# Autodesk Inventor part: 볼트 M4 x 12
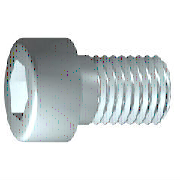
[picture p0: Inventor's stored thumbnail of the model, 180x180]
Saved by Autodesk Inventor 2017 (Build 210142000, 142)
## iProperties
IsCustomPart: 0
Created: 2012-02
Part Number: 볼트 M4 x 12
Material: 강철, 연강
Description: 6각 소켓 머리 캡 나사
Document SubType Name: Modeling
Standard: ISO 4762
Designer: mduedu
Standard Revision: Fourth edition 2004-03-01
Standards Organization: ISO
Language: ko-KR
Size Designation: M4 x 12
Categories: <MemberInstance><Categories><Category DisplayName="조임쇠" InternalName="e4da775c-781d-43d5-af7c-5136215cf5a6" Mnemonic="FSTN"><Category DisplayName="볼트" InternalN
Density: 7.75 g/cm^3
Appearance: 강철
Author: mduedu
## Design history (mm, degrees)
sketch "스케치1"
  geometry: L1 (-1, 0)-(12, 0); L2 (12, 0)-(12, 2); L3 (12, 2)-(1.75, 2); L4 (1.75, 2)-(1.32, 2); L5 (1.32, 2)-(0, 2); L6 (0, 2)-(0, 3.5); L7 (0, 3.5)-(-4, 3.5); L8 (-4, 3.5)-(-4, 1.732); L9 (-4, 1.732)-(-2, 1.732); L10 (-2, 1.732)-(-1, 0); L11 (-7.2, 0)-(15.2, 0) reference; L12 (0, -0.7)-(0, 4.2) reference; L13 (1.75, 2)-(0, 2)
  constraints: 22 end point, 6 parallel, 2 collinear, 2 perpendicular, 1 horizontal, 1 point on line
  dimensions: "d1" = 10.25 distance from line of L3.end L2 (= GEL); "d2" = 0.42952 distance of L4.end L3.end (computed from GAL); "d3" = 4 distance between parallel lines of L8 L6 (= KOH); "d4" = 2 distance of L8.end L9.end (= INTI); "d5" = 60 deg angle of L10 L1; "d6" = 4 diameter of L3 L1 (= GD); "d7" = 4 diameter of L5 L1 (= BDM); "d8" = 3.4641 diameter of L9 L1 (= 1.1547 x SW); "d9" = 7 diameter of L7 L1 (= KOD); "d26" = 12 distance between parallel lines of L12 L2 (= NLG)
revolve "본체" sketch "스케치1" stored, may be unused: angle "d10" = 90 deg
sketch "스케치2"
  geometry: L1 (0, -4.9)-(0, 4.9) reference; L2 (-4.9, 0)-(4.9, 0) reference; L3 (1.732, 0)-(0.866, -1.5); L4 (0.866, -1.5)-(-0.866, -1.5); L5 (-0.866, -1.5)-(-1.732, 0); L6 (-1.732, 0)-(-0.866, 1.5); L7 (-0.866, 1.5)-(0.866, 1.5); L8 (0.866, 1.5)-(1.732, 0); 2 further points
  constraints: 12 end point, 1 coincident, 1 horizontal alignment, 1 point on line, 12 other
extrude "슬롯" join sketch "스케치2" stored distance "d11" = 10; taper "d12" = 0 deg
workplane "Work Plane1"
fillet "Fillet2" dims "d30" = 0.1 (= R)
body "Solid1"
fillet "모깎기1" dims "d17" = 0.4 (= RR)
feature "스레드" dims "d13" = 10.25 (= GEL), "d14" = 0
chamfer "모따기1" distance "d15" = 0.42941 (= -0.5 x SPD + 0.5 x GD); stored, may be unused: second distance "d16" = 0.42941 (= GUL), angle "d27" = 45 deg
other parameters: "GD" = 4 [user parameter; used in 2 equation terms], "NLG" = 12 [user parameter; used in 1 equation term], "GEL" = 10.25 [user parameter; used in 2 equation terms], "KOD" = 7 [user parameter; used in 1 equation term], "KOH" = 4 [user parameter; used in 1 equation term], "INTI" = 2 [user parameter; used in 1 equation term], "GAL" = 0.42941 (= 0.61345 x PTC) [user parameter; used in 1 equation term], "GUL" = 0.42941 (= 0.61345 x PTC) [user parameter; used in 1 equation term], "BDM" = 4 (= NND) [user parameter; used in 1 equation term], "SW" = 3 [user parameter; used in 2 equation terms], "RR" = 0.4 [user parameter; used in 1 equation term], "SPD" = 3.14117 (= NND - 1.2269 x PTC) [user parameter; used in 1 equation term], "d19" = 0, "d28" = 0, "d29" = 0, "R" = 0.1 [user parameter; used in 1 equation term], "TOA" = 30 deg [user parameter], "GD1" = 3.14117 (= THREADDIA - 1.2269 x PTC) [user parameter], "THREADDIA" = 4 [user parameter; used in 1 equation term], "FAWI" = 45 deg [user parameter], "TPU" = 14.28571 (computed from PTC) [user parameter], "PTC" = 0.7 [user parameter; used in 5 equation terms], "NND" = 4 [user parameter; used in 2 equation terms], "E0" = 3.465 (= 1.155 x SW) [user parameter]
